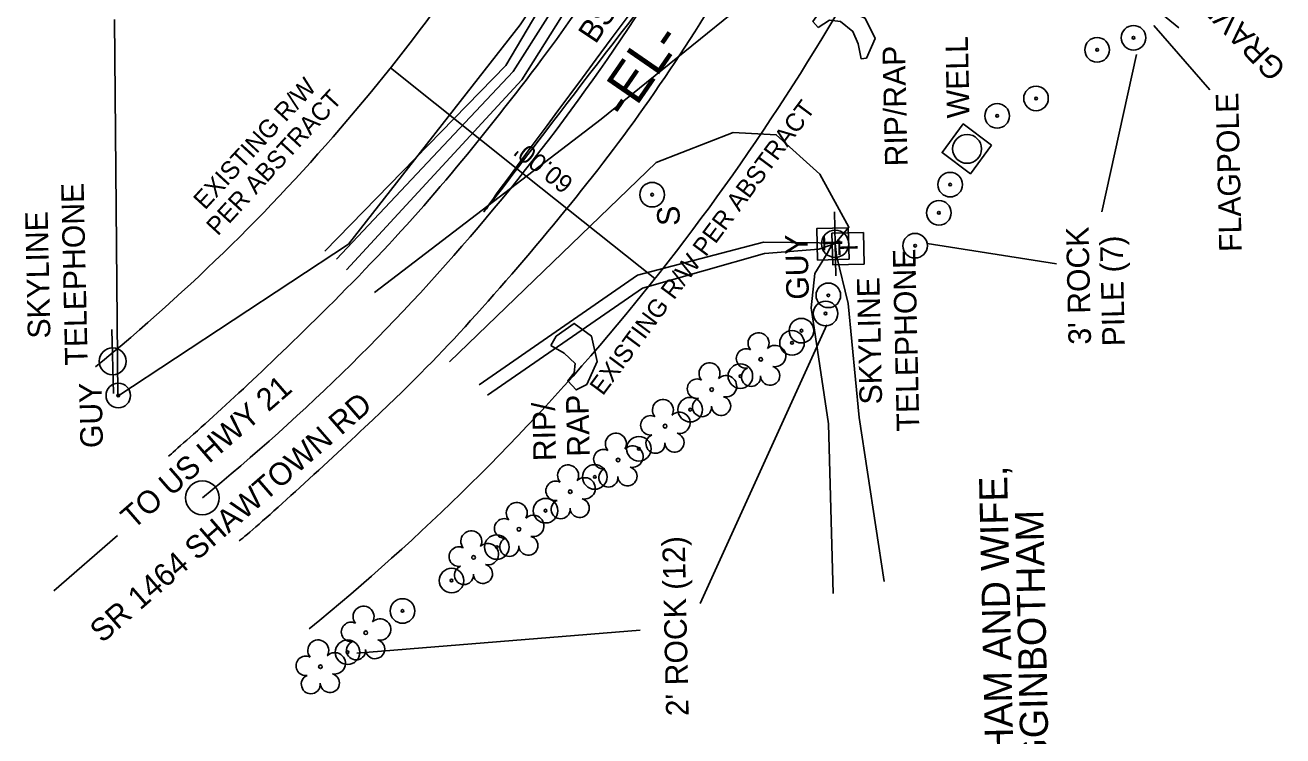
# Model space of a CAD drawing. Extents: x 1417249 to 1417944, y 999313 to 1000321.
# Drawn here: x 1417414.4 to 1417637.7, y 999570.9 to 999696.9 of the extents above; entities that cross this region are included whole.
import ezdxf

# ---------------------------------------------------------------- set-up
doc = ezdxf.new("R2010")
doc.units = 0
for name, color, linetype in [('Exist Horizontal Alignment', 7, 'Continuous'), ('Exist Horizontal Alignment Direction Label', 7, 'Continuous'), ('Exist Horizontal Alignment Point', 7, 'Continuous'), ('Exist Other Culture Anchor (Guy Wire) CELL', 7, 'Continuous'), ('Exist Other Culture Anchor (Guy Wire) Text', 7, 'Continuous'), ('Exist Other Culture Area Outline', 7, 'Continuous'), ('Exist Other Culture Area Outline Text', 7, 'Continuous'), ('Exist Other Culture Located Object CELL', 7, 'Continuous'), ('Exist Other Culture Located Object Leader', 7, 'Continuous'), ('Exist Other Culture Located Object Text', 7, 'Continuous'), ('Exist Other Culture Sign CELL', 7, 'Continuous'), ('Exist Other Culture Sign Text', 7, 'Continuous'), ('Exist Other Culture Well CELL', 7, 'Continuous'), ('Exist Other Culture Well Text', 7, 'Continuous'), ('Exist Property Owner Text', 7, 'Continuous'), ('Exist Right of Way Line', 7, 'Continuous'), ('Exist Right of Way Line Text', 7, 'Continuous'), ('Exist Right of Way Width CELL', 7, 'Continuous'), ('Exist Roads EOP', 7, 'Continuous'), ('Exist Roads EOP Leader', 7, 'Continuous'), ('Exist Roads EOP Other', 7, 'Continuous'), ('Exist Roads EOP Text', 7, 'Continuous'), ('Exist Roads Soil', 7, 'Continuous'), ('Exist Roads Soil Text', 7, 'Continuous'), ('Exist Utilities Other Unknown UG SUE', 7, 'Continuous'), ('Exist Utilities Telephone Pedestal CELL', 7, 'Continuous'), ('Exist Utilities Telephone Pole CELL', 7, 'Continuous'), ('Exist Utilities Telephone Pole Text', 7, 'Continuous'), ('Exist Utilities Telephone UG Cable SUE', 7, 'Continuous'), ('Exist Utilities Telephone UG FO SUE', 7, 'Continuous'), ('Exist Vegetation Tree CELL', 7, 'Continuous'), ('Exist Vegetation Woods Line', 7, 'Continuous')]:
    doc.layers.add(name, color=color, linetype=linetype)

msp = doc.modelspace()

# ---------------------------------------------------------------- linework, layer by layer
at = {"layer": 'Exist Horizontal Alignment'}
msp.add_arc((1417207.54, 999905.42), 377.16, 309.1897, 330.7144, dxfattribs=at)
at = {"layer": 'Exist Horizontal Alignment Point'}
msp.add_circle((1417445.86, 999613.09), 3, dxfattribs=at)
at = {"layer": 'Exist Other Culture Anchor (Guy Wire) CELL'}
for centre, radius in [((1417556.99, 999649), 2.18), ((1417556.99, 999649), 0.24), ((1417430.93, 999631.24), 2.18), ((1417430.93, 999631.24), 0.24)]:
    msp.add_circle(centre, radius, dxfattribs=at)
at = {"layer": 'Exist Other Culture Area Outline'}
for points in [[(1417555.17, 999696.53), (1417554.24, 999697.57), (1417555.52, 999699.42), (1417559.28, 999700.01), (1417563.51, 999698.15), (1417565.3, 999694.57), (1417563.75, 999691.06), (1417562.83, 999690.94), (1417562.29, 999693.6), (1417561.35, 999695.82), (1417559.17, 999697.56), (1417557.17, 999697.83), (1417555.17, 999696.53)], [(1417507.71, 999640.13), (1417508.67, 999641.76), (1417511.87, 999644.02), (1417514.94, 999641.79), (1417515.96, 999637.27), (1417514.14, 999633.21), (1417512.19, 999632.23), (1417510.72, 999633.84), (1417511.86, 999635.27), (1417512.04, 999636.9), (1417510.07, 999638.75), (1417507.71, 999640.13)]]:
    msp.add_lwpolyline(points, dxfattribs=at)
at = {"layer": 'Exist Other Culture Located Object CELL'}
for centre, radius in [((1417611.17, 999694.69), 2.18), ((1417604.71, 999692.55), 2.18), ((1417611.17, 999694.69), 0.24), ((1417604.71, 999692.55), 0.24), ((1417593.86, 999683.93), 2.18), ((1417586.96, 999680.84), 2.18), ((1417593.86, 999683.93), 0.24), ((1417586.96, 999680.84), 0.24), ((1417578.62, 999668.64), 2.18), ((1417578.62, 999668.64), 0.24), ((1417576.62, 999663.64), 2.18), ((1417576.62, 999663.64), 0.24), ((1417572.39, 999657.81), 2.18), ((1417572.39, 999657.81), 0.24), ((1417556.5, 999645.78), 2.18), ((1417552.21, 999642.74), 2.18), ((1417556.5, 999645.78), 0.24), ((1417550.54, 999640.56), 2.18), ((1417552.21, 999642.74), 0.24), ((1417550.54, 999640.56), 0.24), ((1417541.37, 999634.69), 2.18), ((1417541.37, 999634.69), 0.24), ((1417532.47, 999628.73), 2.18), ((1417532.47, 999628.73), 0.24), ((1417523.36, 999621.79), 2.18), ((1417523.36, 999621.79), 0.24), ((1417515.52, 999616.79), 2.18), ((1417515.52, 999616.79), 0.24), ((1417506.79, 999610.81), 2.18), ((1417506.79, 999610.81), 0.24), ((1417498.13, 999604.36), 2.18), ((1417498.13, 999604.36), 0.24), ((1417490.1, 999598.41), 2.18), ((1417490.1, 999598.41), 0.24), ((1417481.39, 999593.02), 2.18), ((1417481.39, 999593.02), 0.24), ((1417471.63, 999585.7), 2.18), ((1417471.63, 999585.7), 0.24)]:
    msp.add_circle(centre, radius, dxfattribs=at)
at = {"layer": 'Exist Other Culture Located Object Leader'}
for points in [[(1417614.8, 999696.86), (1417624.69, 999685.44)], [(1417611.72, 999691.72), (1417605.52, 999663.79)], [(1417574.55, 999658.19), (1417597.52, 999654.57)], [(1417556.73, 999643.75), (1417534.21, 999594.35)], [(1417473.27, 999585.55), (1417523.58, 999589.63)]]:
    msp.add_lwpolyline(points, dxfattribs=at)
at = {"layer": 'Exist Other Culture Sign CELL'}
for radius in [2.18, 0.24]:
    msp.add_circle((1417525.71, 999666.86), radius, dxfattribs=at)
at = {"layer": 'Exist Other Culture Well CELL'}
msp.add_circle((1417581.62, 999674.98), 2.56, dxfattribs=at)
at = {"layer": 'Exist Right of Way Line'}
for radius, end in [(347.16, 330.5684), (407.16, 330.8372)]:
    msp.add_arc((1417207.54, 999905.42), radius, 309.1897, end, dxfattribs=at)
at = {"layer": 'Exist Right of Way Width CELL'}
for p in [(1417479.25, 999689.33), (1417526.21, 999651.98)]:
    msp.add_line(p, (1417503.37, 999670.14), dxfattribs=at)
at = {"layer": 'Exist Roads EOP'}
for points in [[(1417439.85, 999620.47), (1417440.86, 999621.35), (1417448.28, 999627.85), (1417460.93, 999639.72), (1417479.6, 999658.21), (1417494.78, 999676.05), (1417510.16, 999695.92), (1417521.93, 999713.7), (1417532.12, 999735.03), (1417540.79, 999755.62), (1417546.81, 999778.87), (1417552.06, 999801.98), (1417554.17, 999826.56), (1417556.13, 999850.29), (1417555.8, 999866.43), (1417555.64, 999873.66)], [(1417452.41, 999605.46), (1417455.22, 999607.6), (1417478.07, 999628.46), (1417491.77, 999642.25), (1417509.79, 999663.12), (1417524.31, 999681.77), (1417538.87, 999704.21), (1417550.4, 999725.14), (1417560.92, 999751.8), (1417452.41, 999605.46), (1417560.92, 999751.8)]]:
    msp.add_open_spline(points, degree=3, dxfattribs=at)
at = {"layer": 'Exist Roads EOP Leader'}
msp.add_lwpolyline([(1417419.51, 999596.62), (1417430.78, 999606.42)], dxfattribs=at)
at = {"layer": 'Exist Roads EOP Other'}
msp.add_lwpolyline([(1417585.98, 999675.67), (1417580.93, 999679.4), (1417577.17, 999674.32), (1417582.22, 999670.58)], close=True, dxfattribs=at)
at = {"layer": 'Exist Roads Soil'}
msp.add_line((1417614.08, 999700.65), (1417619.22, 999696.44), dxfattribs=at)
at = {"layer": 'Exist Utilities Other Unknown UG SUE'}
msp.add_lwpolyline([(1417476.44, 999649.53), (1417516.66, 999680.26), (1417557.21, 999713.08), (1417565.5, 999720.83)], dxfattribs=at)
at = {"layer": 'Exist Utilities Telephone Pedestal CELL'}
for p, q in [((1417557.77, 999658.05), (1417557.77, 999658.05)), ((1417560.47, 999657.22), (1417560.47, 999657.22))]:
    msp.add_line(p, q, dxfattribs=at)
for points in [[(1417560.67, 999655.4), (1417560.53, 999660.99), (1417554.94, 999660.85), (1417555.07, 999655.26), (1417560.67, 999655.4)], [(1417563.36, 999654.56), (1417563.22, 999660.15), (1417557.63, 999660.02), (1417557.77, 999654.42), (1417563.36, 999654.56)]]:
    msp.add_lwpolyline(points, dxfattribs=at)
at = {"layer": 'Exist Utilities Telephone Pole CELL'}
for p, q in [((1417558.33, 999652.48), (1417558.06, 999663.81)), ((1417558.19, 999658.15), (1417558.19, 999658.15)), ((1417430.06, 999631.62), (1417429.79, 999642.96)), ((1417429.93, 999637.3), (1417429.93, 999637.3))]:
    msp.add_line(p, q, dxfattribs=at)
for centre in [(1417558.19, 999658.15), (1417429.93, 999637.3)]:
    msp.add_circle(centre, 2.41, dxfattribs=at)
at = {"layer": 'Exist Utilities Telephone UG Cable SUE'}
for points in [[(1417469.68, 999655.41), (1417501.04, 999688.68), (1417525.41, 999727.08), (1417542.66, 999770.68), (1417544.91, 999783.26), (1417549.3, 999818.25), (1417550.07, 999858.75), (1417547.47, 999863.17), (1417541.97, 999869.57)], [(1417495, 999633.13), (1417523.11, 999652.6), (1417545.47, 999658.44), (1417555.36, 999658.29), (1417558.19, 999658.18)], [(1417496.48, 999631.3), (1417524, 999650.27), (1417545.67, 999656.41), (1417555.28, 999657.2), (1417558.19, 999658.18)], [(1417557.84, 999596.09), (1417557.01, 999626.19), (1417553.94, 999646.8), (1417554.61, 999652.89), (1417556.78, 999656.4), (1417557.74, 999658.19)], [(1417566.9, 999598.26), (1417562.47, 999627.32), (1417560.5, 999647.53), (1417558.42, 999656.06), (1417558.19, 999658.18)]]:
    msp.add_lwpolyline(points, dxfattribs=at)
at = {"layer": 'Exist Utilities Telephone UG FO SUE'}
for points in [[(1417471.43, 999653.55), (1417502.55, 999687.24), (1417527.4, 999726.75), (1417544.07, 999770.83), (1417552.47, 999820.51), (1417554.12, 999844.53), (1417553.97, 999861.39), (1417555.21, 999863.67), (1417551.27, 999865.18), (1417546.23, 999866.44), (1417543.01, 999868.31), (1417541.06, 999869.26)], [(1417467.59, 999656.83), (1417499.73, 999689.79), (1417522.28, 999727.87), (1417539.9, 999771.2), (1417542.88, 999787.94), (1417546.19, 999818.6), (1417546.93, 999839.08), (1417547.54, 999844.95), (1417549.16, 999846.16), (1417559.4, 999845.4), (1417578.31, 999842.88), (1417592.74, 999843.86), (1417594.44, 999847.99), (1417596.21, 999851.03)], [(1417489.75, 999637.22), (1417526.44, 999672.59), (1417540.1, 999677.88), (1417547.73, 999677.48), (1417555.47, 999670.5), (1417560.63, 999661.11), (1417558.19, 999658.18)]]:
    msp.add_lwpolyline(points, dxfattribs=at)
at = {"layer": 'Exist Vegetation Tree CELL'}
for p, q in [((1417544.99, 999637.65), (1417544.99, 999637.65)), ((1417536.28, 999632.29), (1417536.28, 999632.29)), ((1417528, 999625.8), (1417528, 999625.8)), ((1417519.66, 999619.8), (1417519.66, 999619.8)), ((1417511.17, 999614.18), (1417511.17, 999614.18)), ((1417502.05, 999607.51), (1417502.05, 999607.51)), ((1417494, 999602.51), (1417494, 999602.51)), ((1417474.86, 999589.15), (1417474.86, 999589.15)), ((1417466.81, 999583.14), (1417466.81, 999583.14))]:
    msp.add_line(p, q, dxfattribs=at)
for centre in [(1417544.99, 999637.65), (1417536.28, 999632.29), (1417528, 999625.8), (1417519.66, 999619.8), (1417511.17, 999614.18), (1417502.05, 999607.51), (1417494, 999602.51), (1417474.86, 999589.15), (1417466.81, 999583.14)]:
    msp.add_circle(centre, 0.326, dxfattribs=at)
for centre, radius, start, end in [((1417544.6, 999640.52), 1.86, 330.1651, 219.7134), ((1417542.38, 999637.8), 1.73, 62.6636, 279.3457), ((1417547.53, 999638.24), 1.9, 257.1011, 134.1999), ((1417535.89, 999635.16), 1.86, 330.1651, 219.7134), ((1417543.28, 999634.53), 1.69, 111.5671, 6.231), ((1417546.66, 999634.75), 1.7, 181.2822, 74.56), ((1417533.67, 999632.44), 1.73, 62.6636, 279.3457), ((1417538.82, 999632.88), 1.9, 257.1011, 134.1999), ((1417527.62, 999628.67), 1.86, 330.1651, 219.7134), ((1417534.57, 999629.17), 1.69, 111.5671, 6.231), ((1417537.95, 999629.39), 1.7, 181.2822, 74.56), ((1417525.4, 999625.95), 1.73, 62.6636, 279.3457), ((1417530.55, 999626.39), 1.9, 257.1011, 134.1999), ((1417519.27, 999622.68), 1.86, 330.1651, 219.7134), ((1417526.3, 999622.68), 1.69, 111.5671, 6.231), ((1417529.67, 999622.9), 1.7, 181.2822, 74.56), ((1417517.05, 999619.96), 1.73, 62.6636, 279.3457), ((1417522.21, 999620.39), 1.9, 257.1011, 134.1999), ((1417510.79, 999617.06), 1.86, 330.1651, 219.7134), ((1417517.95, 999616.68), 1.69, 111.5671, 6.231), ((1417521.33, 999616.9), 1.7, 181.2822, 74.56), ((1417508.57, 999614.34), 1.73, 62.6636, 279.3457), ((1417513.72, 999614.77), 1.9, 257.1011, 134.1999), ((1417501.67, 999610.39), 1.86, 330.1651, 219.7134), ((1417509.47, 999611.06), 1.69, 111.5671, 6.231), ((1417512.84, 999611.28), 1.7, 181.2822, 74.56), ((1417499.45, 999607.67), 1.73, 62.6636, 279.3457), ((1417504.6, 999608.1), 1.9, 257.1011, 134.1999), ((1417493.61, 999605.38), 1.86, 330.1651, 219.7134), ((1417496.55, 999603.1), 1.9, 257.1011, 134.1999), ((1417500.35, 999604.39), 1.69, 111.5671, 6.231), ((1417503.73, 999604.61), 1.7, 181.2822, 74.56), ((1417491.39, 999602.66), 1.73, 62.6636, 279.3457), ((1417492.29, 999599.39), 1.69, 111.5671, 6.231), ((1417495.67, 999599.61), 1.7, 181.2822, 74.56), ((1417474.47, 999592.02), 1.86, 330.1651, 219.7134), ((1417477.41, 999589.74), 1.9, 257.1011, 134.1999), ((1417472.25, 999589.3), 1.73, 62.6636, 279.3457), ((1417466.43, 999586.02), 1.86, 330.1651, 219.7134), ((1417473.15, 999586.03), 1.69, 111.5671, 6.231), ((1417476.53, 999586.25), 1.7, 181.2822, 74.56), ((1417464.21, 999583.3), 1.73, 62.6636, 279.3457), ((1417469.36, 999583.73), 1.9, 257.1011, 134.1999), ((1417465.11, 999580.02), 1.69, 111.5671, 6.231), ((1417468.49, 999580.24), 1.7, 181.2822, 74.56)]:
    msp.add_arc(centre, radius, start, end, dxfattribs=at)
at = {"layer": 'Exist Vegetation Woods Line'}
msp.add_lwpolyline([(1417555.22, 999873.36), (1417537.31, 999872.21), (1417538.64, 999847.18), (1417535.89, 999761.69), (1417525.68, 999737.3), (1417519.66, 999723.3), (1417502.28, 999696.97), (1417471.79, 999658.06), (1417430.83, 999631.14), (1417430.26, 999697.93)], dxfattribs=at)

# ---------------------------------------------------------------- texts
at = {"layer": 'Exist Horizontal Alignment Direction Label'}
msp.add_text('-EL-  ', height=7, rotation=55.4168, dxfattribs=at).set_placement((1417521.21, 999679.89))
at = {"layer": 'Exist Other Culture Anchor (Guy Wire) Text'}
for p in [(1417553.55, 999648.28), (1417428.22, 999621.96)]:
    msp.add_text('GUY', height=4, rotation=91.2799, dxfattribs=at).set_placement(p)
at = {"layer": 'Exist Other Culture Area Outline Text'}
for s, p in [('RIP/RAP', (1417571.06, 999671.93)), ('RIP/', (1417508.64, 999619.64)), ('RAP', (1417514.63, 999620.43))]:
    msp.add_text(s, height=4, rotation=91.2799, dxfattribs=at).set_placement(p)
at = {"layer": 'Exist Other Culture Located Object Text'}
for s, p in [("3' ROCK", (1417603.64, 999640.3)), ('PILE (7)', (1417609.64, 999640.02)), ("2' ROCK (12)", (1417532.2, 999574.4))]:
    msp.add_text(s, height=4, rotation=91.2799, dxfattribs=at).set_placement(p)
at = {"layer": 'Exist Other Culture Sign Text'}
for s, p in [('FLAGPOLE', (1417630.39, 999656.75)), ('S', (1417530.63, 999661.37))]:
    msp.add_text(s, height=4, rotation=91.2799, dxfattribs=at).set_placement(p)
at = {"layer": 'Exist Other Culture Well Text'}
msp.add_text('WELL', height=4, rotation=91.2799, dxfattribs=at).set_placement((1417582.07, 999680.47))
at = {"layer": 'Exist Property Owner Text'}
for s, p in [('MANSON SCOTT HIGGINBOTHAM AND WIFE,', (1417591.92, 999474.33)), ('CARA D. ANDERSON-HIGGINBOTHAM', (1417597.84, 999489.54))]:
    msp.add_text(s, height=5, rotation=91.2799, dxfattribs=at).set_placement(p)
at = {"layer": 'Exist Right of Way Line Text'}
for s, rotation, p in [('EXISTING R/W', 47.4024, (1417446.32, 999664.03)), ('PER ABSTRACT', 47.4024, (1417448.61, 999659.42)), ('EXISTING R/W PER ABSTRACT', 53.4156, (1417516.95, 999631.07))]:
    msp.add_text(s, height=3.2, rotation=rotation, dxfattribs=at).set_placement(p)
at = {"layer": 'Exist Right of Way Width CELL'}
msp.add_text("60.00'", height=3.2, rotation=141.5053, dxfattribs=at).set_placement((1417511.97, 999669.34))
at = {"layer": 'Exist Roads EOP Text'}
for s, rotation, p in [('BST', 56.2461, (1417515.66, 999693.44)), ('TO US HWY 21', 40.9954, (1417433.58, 999607.36)), ('SR 1464 SHAWTOWN RD', 40.9954, (1417428.07, 999587.2))]:
    msp.add_text(s, height=4, rotation=rotation, dxfattribs=at).set_placement(p)
at = {"layer": 'Exist Roads Soil Text'}
msp.add_text('GRAVEL', height=4, rotation=134.026, dxfattribs=at).set_placement((1417638.49, 999689.44))
at = {"layer": 'Exist Utilities Telephone Pedestal CELL'}
for p in [(1417559.52, 999656.96), (1417562.21, 999656.13)]:
    msp.add_text('T', height=3.42, rotation=91.3853, dxfattribs=at).set_placement(p)
at = {"layer": 'Exist Utilities Telephone Pole Text'}
for s, p in [('TELEPHONE', (1417425.5, 999636.61)), ('SKYLINE', (1417418.89, 999641.38)), ('TELEPHONE', (1417573.15, 999624.92)), ('SKYLINE', (1417566.55, 999629.69))]:
    msp.add_text(s, height=4, rotation=91.2799, dxfattribs=at).set_placement(p)

doc.saveas('drawing.dxf')
